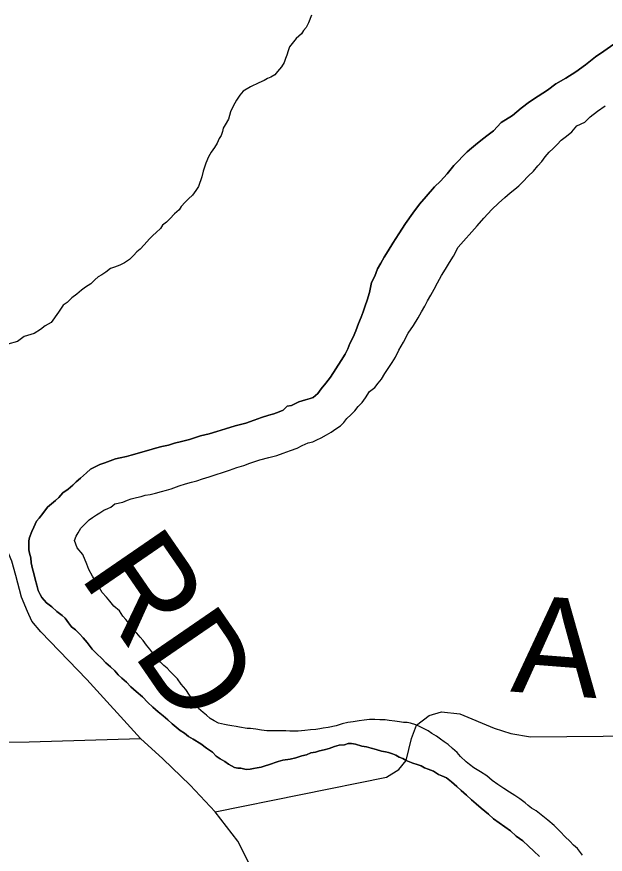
# Model space of a CAD drawing. Extents: x 0 to 34, y 0 to 22.
# Drawn here: x 5.4862 to 5.8289, y 16.1473 to 16.6354 of the extents above; entities that cross this region are included whole.
import ezdxf

# ---------------------------------------------------------------- set-up
doc = ezdxf.new("R2010")
doc.units = 0
for name, color, linetype in [('GM_X_Major_River', 7, 'Continuous'), ('GM_X_Minor_River', 7, 'Continuous'), ('GM_X_Township_Road', 7, 'Continuous'), ('GM_X_Township_Road_Text', 7, 'Continuous')]:
    doc.layers.add(name, color=color, linetype=linetype)

msp = doc.modelspace()

# ---------------------------------------------------------------- linework, layer by layer
at = {"layer": 'GM_X_Major_River'}
for points in [[(5.83393, 16.61948), (5.82818, 16.61537), (5.82319, 16.61201), (5.81744, 16.60751), (5.81169, 16.6034), (5.80594, 16.59966), (5.8002, 16.59631), (5.79521, 16.59257), (5.78985, 16.58921), (5.78487, 16.58585), (5.77988, 16.58211), (5.77489, 16.57798), (5.76838, 16.57388), (5.76375, 16.56899), (5.75992, 16.566), (5.75647, 16.56338), (5.75339, 16.56075), (5.75109, 16.55888), (5.7484, 16.55663), (5.7407, 16.54874), (5.73684, 16.54384), (5.73299, 16.53971), (5.72953, 16.53633), (5.72452, 16.53069), (5.72067, 16.52617), (5.7168, 16.5209), (5.71255, 16.51486), (5.70867, 16.50883), (5.70519, 16.50355), (5.70247, 16.49902), (5.70015, 16.49524), (5.69821, 16.49184), (5.69626, 16.48845), (5.69469, 16.48428), (5.69275, 16.48051), (5.69154, 16.47482), (5.69034, 16.47027)], [(5.69034, 16.47027), (5.69154, 16.47482), (5.69275, 16.48051), (5.69469, 16.48428), (5.69626, 16.48845), (5.69821, 16.49184), (5.70015, 16.49524), (5.70247, 16.49902), (5.70519, 16.50355), (5.70867, 16.50883), (5.71255, 16.51486), (5.7168, 16.5209), (5.72067, 16.52617), (5.72452, 16.53069), (5.72953, 16.53633), (5.73299, 16.53971), (5.73684, 16.54384), (5.7407, 16.54874), (5.7484, 16.55663), (5.75109, 16.55888), (5.75339, 16.56075), (5.75647, 16.56338), (5.75992, 16.566), (5.76375, 16.56899), (5.76838, 16.57388), (5.77489, 16.57798), (5.77988, 16.58211), (5.78487, 16.58585), (5.78985, 16.58921), (5.79521, 16.59257), (5.8002, 16.59631), (5.80594, 16.59966), (5.81169, 16.6034), (5.81744, 16.60751), (5.82319, 16.61201), (5.82818, 16.61537), (5.83393, 16.61948)], [(5.80629, 16.56583), (5.80937, 16.56845), (5.81245, 16.57184), (5.81704, 16.57406), (5.82011, 16.57707), (5.82433, 16.58044), (5.82893, 16.58343)], [(5.80629, 16.56583), (5.80937, 16.56845), (5.81245, 16.57184), (5.81704, 16.57406), (5.82011, 16.57707), (5.82433, 16.58044), (5.82893, 16.58343)], [(5.52472, 16.32208), (5.52135, 16.32593), (5.51988, 16.33012), (5.52067, 16.33278), (5.52183, 16.33466), (5.52338, 16.3373), (5.52608, 16.33993), (5.52839, 16.34219), (5.5303, 16.34369), (5.5326, 16.34518), (5.53452, 16.3463), (5.53682, 16.34779), (5.53911, 16.3489), (5.54102, 16.34964), (5.54332, 16.35151), (5.5479, 16.3526), (5.55057, 16.35371), (5.55286, 16.35444), (5.55591, 16.35516), (5.55858, 16.35589), (5.56087, 16.35663), (5.56391, 16.35697), (5.56697, 16.35769), (5.5704, 16.3588), (5.57345, 16.35952), (5.57612, 16.36025), (5.5807, 16.36209), (5.58452, 16.36319), (5.58795, 16.36429), (5.591, 16.36501), (5.59443, 16.36611), (5.59825, 16.36721), (5.61008, 16.37125), (5.61428, 16.37272), (5.61848, 16.37381), (5.62192, 16.37529), (5.62764, 16.37712), (5.63298, 16.37858), (5.63755, 16.37966), (5.64137, 16.38114), (5.64557, 16.38261), (5.64939, 16.38409), (5.65245, 16.38557), (5.65589, 16.38705), (5.65856, 16.38778), (5.66085, 16.38889), (5.66353, 16.39), (5.66659, 16.39187), (5.66927, 16.39335), (5.67195, 16.39522), (5.67464, 16.39709), (5.67656, 16.39897), (5.67849, 16.40123), (5.68079, 16.40348), (5.6831, 16.40573), (5.68504, 16.40837), (5.68734, 16.41063), (5.68928, 16.41327), (5.6916, 16.41704), (5.69467, 16.41928), (5.6966, 16.42192), (5.69853, 16.42418), (5.70047, 16.42758), (5.70279, 16.43097), (5.70473, 16.43399), (5.70667, 16.43701), (5.70862, 16.44116), (5.71133, 16.44569), (5.71406, 16.45098), (5.71715, 16.45551), (5.71987, 16.46004), (5.72181, 16.46344), (5.72375, 16.46684), (5.72531, 16.46986), (5.72725, 16.47326), (5.72919, 16.47665), (5.73114, 16.48043), (5.73347, 16.48459), (5.7358, 16.48836), (5.73812, 16.49213), (5.74045, 16.49591), (5.74317, 16.50119), (5.75435, 16.51361), (5.7582, 16.51812), (5.76282, 16.52301), (5.76667, 16.52677), (5.77051, 16.53014), (5.77358, 16.53277), (5.77627, 16.53502), (5.77857, 16.53689), (5.78088, 16.53914), (5.78397, 16.54253), (5.78704, 16.54553), (5.78974, 16.54854), (5.79205, 16.55117), (5.79398, 16.55381), (5.7963, 16.55644), (5.79861, 16.5587), (5.80091, 16.56095), (5.80322, 16.56359), (5.80629, 16.56583)], [(5.52472, 16.32208), (5.52135, 16.32593), (5.51988, 16.33012), (5.52067, 16.33278), (5.52183, 16.33466), (5.52338, 16.3373), (5.52608, 16.33993), (5.52839, 16.34219), (5.5303, 16.34369), (5.5326, 16.34518), (5.53452, 16.3463), (5.53682, 16.34779), (5.53911, 16.3489), (5.54102, 16.34964), (5.54332, 16.35151), (5.5479, 16.3526), (5.55057, 16.35371), (5.55286, 16.35444), (5.55591, 16.35516), (5.55858, 16.35589), (5.56087, 16.35663), (5.56391, 16.35697), (5.56697, 16.35769), (5.5704, 16.3588), (5.57345, 16.35952), (5.57612, 16.36025), (5.5807, 16.36209), (5.58452, 16.36319), (5.58795, 16.36429), (5.591, 16.36501), (5.59443, 16.36611), (5.59825, 16.36721), (5.61008, 16.37125), (5.61428, 16.37272), (5.61848, 16.37381), (5.62192, 16.37529), (5.62764, 16.37712), (5.63298, 16.37858), (5.63755, 16.37966), (5.64137, 16.38114), (5.64557, 16.38261), (5.64939, 16.38409), (5.65245, 16.38557), (5.65589, 16.38705), (5.65856, 16.38778), (5.66085, 16.38889), (5.66353, 16.39), (5.66659, 16.39187), (5.66927, 16.39335), (5.67195, 16.39522), (5.67464, 16.39709), (5.67656, 16.39897), (5.67849, 16.40123), (5.68079, 16.40348), (5.6831, 16.40573), (5.68504, 16.40837), (5.68734, 16.41063), (5.68928, 16.41327), (5.6916, 16.41704), (5.69467, 16.41928), (5.6966, 16.42192), (5.69853, 16.42418), (5.70047, 16.42758), (5.70279, 16.43097), (5.70473, 16.43399), (5.70667, 16.43701), (5.70862, 16.44116), (5.71133, 16.44569), (5.71406, 16.45098), (5.71715, 16.45551), (5.71987, 16.46004), (5.72181, 16.46344), (5.72375, 16.46684), (5.72531, 16.46986), (5.72725, 16.47326), (5.72919, 16.47665), (5.73114, 16.48043), (5.73347, 16.48459), (5.7358, 16.48836), (5.73812, 16.49213), (5.74045, 16.49591), (5.74317, 16.50119), (5.75435, 16.51361), (5.7582, 16.51812), (5.76282, 16.52301), (5.76667, 16.52677), (5.77051, 16.53014), (5.77358, 16.53277), (5.77627, 16.53502), (5.77857, 16.53689), (5.78088, 16.53914), (5.78397, 16.54253), (5.78704, 16.54553), (5.78974, 16.54854), (5.79205, 16.55117), (5.79398, 16.55381), (5.7963, 16.55644), (5.79861, 16.5587), (5.80091, 16.56095), (5.80322, 16.56359), (5.80629, 16.56583)], [(5.69034, 16.47027), (5.68916, 16.46687), (5.68798, 16.46346), (5.6868, 16.46043), (5.68524, 16.45665), (5.68367, 16.45248), (5.6821, 16.4487), (5.68015, 16.44492), (5.67898, 16.4419), (5.67742, 16.43887), (5.67509, 16.4351), (5.66889, 16.42529), (5.66619, 16.4219), (5.66349, 16.41851), (5.66156, 16.41587), (5.65887, 16.41362), (5.65696, 16.41289), (5.65429, 16.41216), (5.65048, 16.41106), (5.64627, 16.40883), (5.6436, 16.40848), (5.64129, 16.40623), (5.639, 16.40512), (5.63595, 16.40401), (5.6329, 16.40329), (5.6287, 16.40182), (5.6245, 16.40035), (5.61953, 16.39851), (5.61343, 16.39706), (5.60771, 16.39523), (5.60275, 16.39376), (5.59817, 16.3923), (5.59322, 16.39121), (5.58673, 16.38901), (5.58215, 16.38792), (5.57796, 16.38683), (5.57453, 16.38573), (5.57072, 16.38502), (5.5669, 16.38393), (5.56309, 16.38283), (5.55279, 16.37991), (5.55012, 16.37918), (5.54631, 16.37847), (5.54364, 16.37774), (5.54058, 16.37663), (5.53753, 16.37553), (5.53447, 16.37443), (5.53218, 16.37331), (5.52912, 16.37183), (5.52681, 16.36958), (5.52336, 16.36657), (5.52067, 16.36433), (5.51875, 16.36245), (5.51606, 16.3602), (5.51299, 16.35795), (5.51068, 16.35532), (5.50875, 16.35344), (5.50645, 16.35157), (5.50415, 16.3497), (5.50144, 16.34593), (5.49913, 16.3433), (5.49758, 16.34141), (5.49602, 16.33801), (5.49485, 16.33536), (5.49367, 16.33195), (5.49327, 16.33006), (5.49324, 16.32778), (5.4932, 16.32474), (5.49356, 16.32283), (5.49429, 16.32016), (5.49463, 16.31712), (5.49535, 16.31369), (5.49608, 16.31102), (5.4968, 16.30759), (5.4979, 16.30416), (5.49862, 16.30111), (5.49973, 16.29881), (5.50085, 16.2969), (5.50347, 16.29383), (5.50649, 16.29151), (5.5095, 16.28881), (5.51251, 16.2865), (5.51439, 16.28495), (5.51626, 16.28227), (5.51813, 16.27997), (5.52039, 16.27804), (5.52264, 16.27573), (5.5249, 16.27342), (5.52714, 16.27074), (5.53014, 16.2669), (5.53277, 16.26421), (5.53578, 16.26151), (5.53803, 16.25882), (5.54066, 16.25651), (5.54329, 16.2542), (5.54516, 16.2519), (5.54742, 16.24997), (5.55006, 16.24766), (5.55268, 16.24497), (5.55569, 16.24227), (5.55946, 16.23918)], [(5.55946, 16.23918), (5.55569, 16.24227), (5.55268, 16.24497), (5.55006, 16.24766), (5.54742, 16.24997), (5.54516, 16.2519), (5.54329, 16.2542), (5.54066, 16.25651), (5.53803, 16.25882), (5.53578, 16.26151), (5.53277, 16.26421), (5.53014, 16.2669), (5.52714, 16.27074), (5.5249, 16.27342), (5.52264, 16.27573), (5.52039, 16.27804), (5.51813, 16.27997), (5.51626, 16.28227), (5.51439, 16.28495), (5.51251, 16.2865), (5.5095, 16.28881), (5.50649, 16.29151), (5.50347, 16.29383), (5.50085, 16.2969), (5.49973, 16.29881), (5.49862, 16.30111), (5.4979, 16.30416), (5.4968, 16.30759), (5.49608, 16.31102), (5.49535, 16.31369), (5.49463, 16.31712), (5.49429, 16.32016), (5.49356, 16.32283), (5.4932, 16.32474), (5.49324, 16.32778), (5.49327, 16.33006), (5.49367, 16.33195), (5.49485, 16.33536), (5.49602, 16.33801), (5.49758, 16.34141), (5.49913, 16.3433), (5.50144, 16.34593), (5.50415, 16.3497), (5.50645, 16.35157), (5.50875, 16.35344), (5.51068, 16.35532), (5.51299, 16.35795), (5.51606, 16.3602), (5.51875, 16.36245), (5.52067, 16.36433), (5.52336, 16.36657), (5.52681, 16.36958), (5.52912, 16.37183), (5.53218, 16.37331), (5.53447, 16.37443), (5.53753, 16.37553), (5.54058, 16.37663), (5.54364, 16.37774), (5.54631, 16.37847), (5.55012, 16.37918), (5.55279, 16.37991), (5.56309, 16.38283), (5.5669, 16.38393), (5.57072, 16.38502), (5.57453, 16.38573), (5.57796, 16.38683), (5.58215, 16.38792), (5.58673, 16.38901), (5.59322, 16.39121), (5.59817, 16.3923), (5.60275, 16.39376), (5.60771, 16.39523), (5.61343, 16.39706), (5.61953, 16.39851), (5.6245, 16.40035), (5.6287, 16.40182), (5.6329, 16.40329), (5.63595, 16.40401), (5.639, 16.40512), (5.64129, 16.40623), (5.6436, 16.40848), (5.64627, 16.40883), (5.65048, 16.41106), (5.65429, 16.41216), (5.65696, 16.41289), (5.65887, 16.41362), (5.66156, 16.41587), (5.66349, 16.41851), (5.66619, 16.4219), (5.66889, 16.42529), (5.67509, 16.4351), (5.67742, 16.43887), (5.67898, 16.4419), (5.68015, 16.44492), (5.6821, 16.4487), (5.68367, 16.45248), (5.68524, 16.45665), (5.6868, 16.46043), (5.68798, 16.46346), (5.68916, 16.46687), (5.69034, 16.47027)], [(5.7762, 16.1815), (5.77318, 16.18343), (5.76979, 16.18575), (5.76639, 16.18807), (5.763, 16.1904), (5.76, 16.19309), (5.75622, 16.19542), (5.75245, 16.19774), (5.74981, 16.19967), (5.74793, 16.20122), (5.74454, 16.2043), (5.74267, 16.2066), (5.74004, 16.20891), (5.7374, 16.21123), (5.73514, 16.21277), (5.73288, 16.21432), (5.73062, 16.21625), (5.72798, 16.2178), (5.72572, 16.21935), (5.72345, 16.22051), (5.72118, 16.22168), (5.71854, 16.22285), (5.71551, 16.22365), (5.71361, 16.22405), (5.71133, 16.22408), (5.70905, 16.22449), (5.7064, 16.2249), (5.70298, 16.22532), (5.70071, 16.22572), (5.69766, 16.22576), (5.69462, 16.2258), (5.69158, 16.22583), (5.68854, 16.22549), (5.68549, 16.22515), (5.68206, 16.22443), (5.67902, 16.22408), (5.67559, 16.22336), (5.67215, 16.22226), (5.66758, 16.22118), (5.66453, 16.22083), (5.66263, 16.22048), (5.66034, 16.22012), (5.6573, 16.21978), (5.65387, 16.21944), (5.65007, 16.2191), (5.64741, 16.21913), (5.64513, 16.21916), (5.64285, 16.21919), (5.63981, 16.21923), (5.63638, 16.21927), (5.63182, 16.21932), (5.62879, 16.21974), (5.62537, 16.22016), (5.62234, 16.22057), (5.62043, 16.22059), (5.61588, 16.22141), (5.61399, 16.22181), (5.61133, 16.22222), (5.60906, 16.22263), (5.60716, 16.22303), (5.60375, 16.22383), (5.6011, 16.22501), (5.59884, 16.22655), (5.59658, 16.22848), (5.5947, 16.23002), (5.59207, 16.23234), (5.59095, 16.23463), (5.58908, 16.23693), (5.58684, 16.24), (5.5846, 16.24345), (5.58197, 16.24652), (5.57973, 16.24959), (5.57748, 16.25189), (5.5756, 16.25382), (5.57372, 16.25574), (5.57184, 16.25728), (5.56996, 16.2592), (5.56847, 16.2615), (5.56547, 16.26458), (5.56359, 16.26688), (5.56172, 16.26919), (5.55985, 16.27187), (5.55797, 16.27379), (5.5561, 16.2761), (5.5546, 16.27802), (5.55311, 16.27993), (5.55161, 16.28185), (5.54973, 16.28416), (5.54786, 16.28608), (5.54599, 16.28914), (5.5426, 16.29184), (5.54036, 16.29491), (5.53849, 16.29721), (5.53586, 16.2999), (5.53437, 16.30258), (5.53288, 16.30488), (5.53139, 16.30756), (5.53027, 16.30947), (5.52804, 16.3133), (5.52693, 16.31635), (5.52472, 16.32208)], [(5.7762, 16.1815), (5.77318, 16.18343), (5.76979, 16.18575), (5.76639, 16.18807), (5.763, 16.1904), (5.76, 16.19309), (5.75622, 16.19542), (5.75245, 16.19774), (5.74981, 16.19967), (5.74793, 16.20122), (5.74454, 16.2043), (5.74267, 16.2066), (5.74004, 16.20891), (5.7374, 16.21123), (5.73514, 16.21277), (5.73288, 16.21432), (5.73062, 16.21625), (5.72798, 16.2178), (5.72572, 16.21935), (5.72345, 16.22051), (5.72118, 16.22168), (5.71854, 16.22285), (5.71551, 16.22365), (5.71361, 16.22405), (5.71133, 16.22408), (5.70905, 16.22449), (5.7064, 16.2249), (5.70298, 16.22532), (5.70071, 16.22572), (5.69766, 16.22576), (5.69462, 16.2258), (5.69158, 16.22583), (5.68854, 16.22549), (5.68549, 16.22515), (5.68206, 16.22443), (5.67902, 16.22408), (5.67559, 16.22336), (5.67215, 16.22226), (5.66758, 16.22118), (5.66453, 16.22083), (5.66263, 16.22048), (5.66034, 16.22012), (5.6573, 16.21978), (5.65387, 16.21944), (5.65007, 16.2191), (5.64741, 16.21913), (5.64513, 16.21916), (5.64285, 16.21919), (5.63981, 16.21923), (5.63638, 16.21927), (5.63182, 16.21932), (5.62879, 16.21974), (5.62537, 16.22016), (5.62234, 16.22057), (5.62043, 16.22059), (5.61588, 16.22141), (5.61399, 16.22181), (5.61133, 16.22222), (5.60906, 16.22263), (5.60716, 16.22303), (5.60375, 16.22383), (5.6011, 16.22501), (5.59884, 16.22655), (5.59658, 16.22848), (5.5947, 16.23002), (5.59207, 16.23234), (5.59095, 16.23463), (5.58908, 16.23693), (5.58684, 16.24), (5.5846, 16.24345), (5.58197, 16.24652), (5.57973, 16.24959), (5.57748, 16.25189), (5.5756, 16.25382), (5.57372, 16.25574), (5.57184, 16.25728), (5.56996, 16.2592), (5.56847, 16.2615), (5.56547, 16.26458), (5.56359, 16.26688), (5.56172, 16.26919), (5.55985, 16.27187), (5.55797, 16.27379), (5.5561, 16.2761), (5.5546, 16.27802), (5.55311, 16.27993), (5.55161, 16.28185), (5.54973, 16.28416), (5.54786, 16.28608), (5.54599, 16.28914), (5.5426, 16.29184), (5.54036, 16.29491), (5.53849, 16.29721), (5.53586, 16.2999), (5.53437, 16.30258), (5.53288, 16.30488), (5.53139, 16.30756), (5.53027, 16.30947), (5.52804, 16.3133), (5.52693, 16.31635), (5.52472, 16.32208)], [(5.55946, 16.23918), (5.56246, 16.23573), (5.56547, 16.23303), (5.56847, 16.23033), (5.57149, 16.22802), (5.57412, 16.22571), (5.57675, 16.22339), (5.57901, 16.22147), (5.58127, 16.21954), (5.58391, 16.21799), (5.58617, 16.21606), (5.58881, 16.21451), (5.59334, 16.21179), (5.59673, 16.20909), (5.60012, 16.20677), (5.60237, 16.20446), (5.60464, 16.20292), (5.60728, 16.20136), (5.60954, 16.19982), (5.61294, 16.19787), (5.61483, 16.19747), (5.61674, 16.19745), (5.61977, 16.19666), (5.62205, 16.19701), (5.62396, 16.19737), (5.62624, 16.19772), (5.62853, 16.19807), (5.63082, 16.1988), (5.63273, 16.19954), (5.63845, 16.20137), (5.64112, 16.2021), (5.64531, 16.20281), (5.64874, 16.20353), (5.65218, 16.20463), (5.65485, 16.20536), (5.65752, 16.20647), (5.66018, 16.20682), (5.66247, 16.20755), (5.66514, 16.20828), (5.66819, 16.209), (5.67125, 16.21011), (5.67392, 16.21084), (5.67696, 16.21118), (5.67925, 16.21191), (5.68115, 16.21189), (5.68343, 16.21148), (5.68722, 16.2103), (5.68987, 16.20989), (5.69252, 16.20909), (5.69555, 16.2083), (5.69859, 16.2075), (5.70086, 16.2071), (5.70276, 16.20669), (5.70503, 16.20591), (5.70692, 16.20512), (5.70881, 16.20396), (5.71108, 16.20317), (5.71297, 16.20201), (5.71486, 16.20123), (5.71675, 16.20045), (5.7194, 16.19966), (5.72167, 16.19887), (5.72356, 16.1977), (5.72583, 16.19692), (5.72886, 16.19574), (5.73187, 16.1938), (5.73376, 16.19302), (5.73641, 16.19185), (5.73942, 16.18953), (5.74243, 16.18684), (5.74507, 16.18452), (5.74807, 16.18183), (5.75108, 16.17913), (5.75372, 16.17682), (5.75672, 16.17412), (5.76086, 16.17065), (5.76387, 16.16796), (5.77367, 16.161), (5.77706, 16.15792), (5.78082, 16.15521), (5.78421, 16.15213), (5.78722, 16.14905), (5.7906, 16.14597)], [(5.7906, 16.14597), (5.78722, 16.14905), (5.78421, 16.15213), (5.78082, 16.15521), (5.77706, 16.15792), (5.77367, 16.161), (5.76387, 16.16796), (5.76086, 16.17065), (5.75672, 16.17412), (5.75372, 16.17682), (5.75108, 16.17913), (5.74807, 16.18183), (5.74507, 16.18452), (5.74243, 16.18684), (5.73942, 16.18953), (5.73641, 16.19185), (5.73376, 16.19302), (5.73187, 16.1938), (5.72886, 16.19574), (5.72583, 16.19692), (5.72356, 16.1977), (5.72167, 16.19887), (5.7194, 16.19966), (5.71675, 16.20045), (5.71486, 16.20123), (5.71297, 16.20201), (5.71108, 16.20317), (5.70881, 16.20396), (5.70692, 16.20512), (5.70503, 16.20591), (5.70276, 16.20669), (5.70086, 16.2071), (5.69859, 16.2075), (5.69555, 16.2083), (5.69252, 16.20909), (5.68987, 16.20989), (5.68722, 16.2103), (5.68343, 16.21148), (5.68115, 16.21189), (5.67925, 16.21191), (5.67696, 16.21118), (5.67392, 16.21084), (5.67125, 16.21011), (5.66819, 16.209), (5.66514, 16.20828), (5.66247, 16.20755), (5.66018, 16.20682), (5.65752, 16.20647), (5.65485, 16.20536), (5.65218, 16.20463), (5.64874, 16.20353), (5.64531, 16.20281), (5.64112, 16.2021), (5.63845, 16.20137), (5.63273, 16.19954), (5.63082, 16.1988), (5.62853, 16.19807), (5.62624, 16.19772), (5.62396, 16.19737), (5.62205, 16.19701), (5.61977, 16.19666), (5.61674, 16.19745), (5.61483, 16.19747), (5.61294, 16.19787), (5.60954, 16.19982), (5.60728, 16.20136), (5.60464, 16.20292), (5.60237, 16.20446), (5.60012, 16.20677), (5.59673, 16.20909), (5.59334, 16.21179), (5.58881, 16.21451), (5.58617, 16.21606), (5.58391, 16.21799), (5.58127, 16.21954), (5.57901, 16.22147), (5.57675, 16.22339), (5.57412, 16.22571), (5.57149, 16.22802), (5.56847, 16.23033), (5.56547, 16.23303), (5.56246, 16.23573), (5.55946, 16.23918)], [(5.8157, 16.14682), (5.8127, 16.15065), (5.81044, 16.15258), (5.80819, 16.15489), (5.80556, 16.15758), (5.80256, 16.16066), (5.79918, 16.16412), (5.79541, 16.1672), (5.79165, 16.17029), (5.78864, 16.17261), (5.786, 16.17416), (5.78411, 16.1757), (5.78223, 16.17724), (5.77922, 16.17956), (5.7762, 16.1815)], [(5.8157, 16.14682), (5.8127, 16.15065), (5.81044, 16.15258), (5.80819, 16.15489), (5.80556, 16.15758), (5.80256, 16.16066), (5.79918, 16.16412), (5.79541, 16.1672), (5.79165, 16.17029), (5.78864, 16.17261), (5.786, 16.17416), (5.78411, 16.1757), (5.78223, 16.17724), (5.77922, 16.17956), (5.7762, 16.1815)]]:
    msp.add_lwpolyline(points, dxfattribs=at)
at = {"layer": 'GM_X_Minor_River'}
msp.add_lwpolyline([(5.65775, 16.63639), (5.65617, 16.63185), (5.65462, 16.62921), (5.65308, 16.62733), (5.65191, 16.62544), (5.64884, 16.62282), (5.64653, 16.6198), (5.64498, 16.61792), (5.64419, 16.61565), (5.6434, 16.613), (5.64262, 16.6111), (5.64183, 16.60883), (5.64028, 16.60619), (5.63797, 16.60356), (5.63642, 16.60167), (5.63412, 16.60018), (5.63222, 16.59944), (5.6303, 16.59833), (5.62724, 16.59684), (5.62227, 16.59462), (5.61806, 16.59201), (5.61613, 16.58975), (5.6142, 16.58673), (5.61225, 16.58334), (5.61069, 16.57993), (5.6095, 16.57577), (5.60756, 16.57237), (5.6064, 16.57048), (5.60599, 16.56859), (5.60521, 16.56631), (5.60404, 16.56442), (5.60287, 16.56178), (5.60132, 16.55914), (5.59939, 16.5565), (5.59783, 16.55386), (5.59627, 16.55007), (5.59469, 16.54553), (5.59389, 16.54212), (5.59192, 16.53644), (5.59038, 16.53418), (5.58844, 16.53154), (5.58613, 16.52929), (5.58421, 16.52741), (5.5819, 16.52478), (5.58074, 16.52289), (5.57805, 16.52064), (5.57535, 16.51763), (5.57343, 16.51575), (5.57112, 16.51388), (5.56996, 16.51199), (5.56727, 16.50974), (5.56535, 16.50787), (5.56343, 16.50599), (5.56034, 16.5026), (5.55803, 16.49997), (5.55611, 16.49847), (5.55418, 16.49621), (5.55188, 16.49396), (5.54882, 16.4921), (5.54614, 16.49061), (5.54308, 16.4895), (5.54079, 16.48877), (5.5381, 16.48652), (5.5358, 16.48503), (5.53351, 16.48391), (5.53159, 16.48204), (5.52928, 16.47978), (5.52622, 16.47792), (5.52391, 16.47605), (5.52122, 16.4738), (5.51816, 16.47155), (5.51547, 16.46892), (5.51316, 16.46743), (5.51045, 16.46328), (5.5062, 16.45725), (5.50276, 16.45539), (5.50007, 16.45314), (5.49624, 16.45091), (5.49052, 16.44907), (5.48668, 16.44608), (5.48096, 16.44462)], dxfattribs=at)
at = {"layer": 'GM_X_Township_Road'}
for points in [[(5.55831, 16.21486), (5.52701, 16.24918), (5.50022, 16.27703), (5.49494, 16.28313), (5.49232, 16.28884), (5.48895, 16.29721), (5.48559, 16.30975), (5.48336, 16.31812), (5.47586, 16.33524), (5.40941, 16.47265), (5.35124, 16.59558), (5.3396, 16.61994), (5.32609, 16.64735), (5.27129, 16.76267), (5.25291, 16.80301), (5.24444, 16.82177)], [(5.6017, 16.17213), (5.70149, 16.19218), (5.70871, 16.1967), (5.71291, 16.202), (5.716, 16.21489), (5.71907, 16.22248), (5.7263, 16.22814), (5.73351, 16.23039), (5.74412, 16.2292), (5.76417, 16.22075), (5.77384, 16.21773), (5.78538, 16.21572), (5.97606, 16.21751), (6.20162, 16.21877), (6.53442, 16.22672), (6.93852, 16.22879)], [(5.17842, 16.22124), (5.36838, 16.21268), (5.49347, 16.21288), (5.55831, 16.21486)], [(5.55831, 16.21486), (5.57114, 16.20303), (5.58718, 16.18755), (5.6017, 16.17213)], [(5.73595, 15.86731), (5.73033, 15.88062), (5.72059, 15.9046), (5.7041, 15.94455), (5.68049, 16.00086), (5.64601, 16.08381), (5.62164, 16.14165), (5.61488, 16.15498), (5.6017, 16.17213)]]:
    msp.add_lwpolyline(points, dxfattribs=at)

# ---------------------------------------------------------------- texts
at = {"layer": 'GM_X_Township_Road_Text'}
for s, height, rotation, p in [('RD', 0.056818, 304.5091, (5.52211, 16.30972)), ('A', 0.05682, 355.5443, (5.77341, 16.24221))]:
    msp.add_text(s, height=height, rotation=rotation, dxfattribs=at).set_placement(p)

doc.saveas('drawing.dxf')
